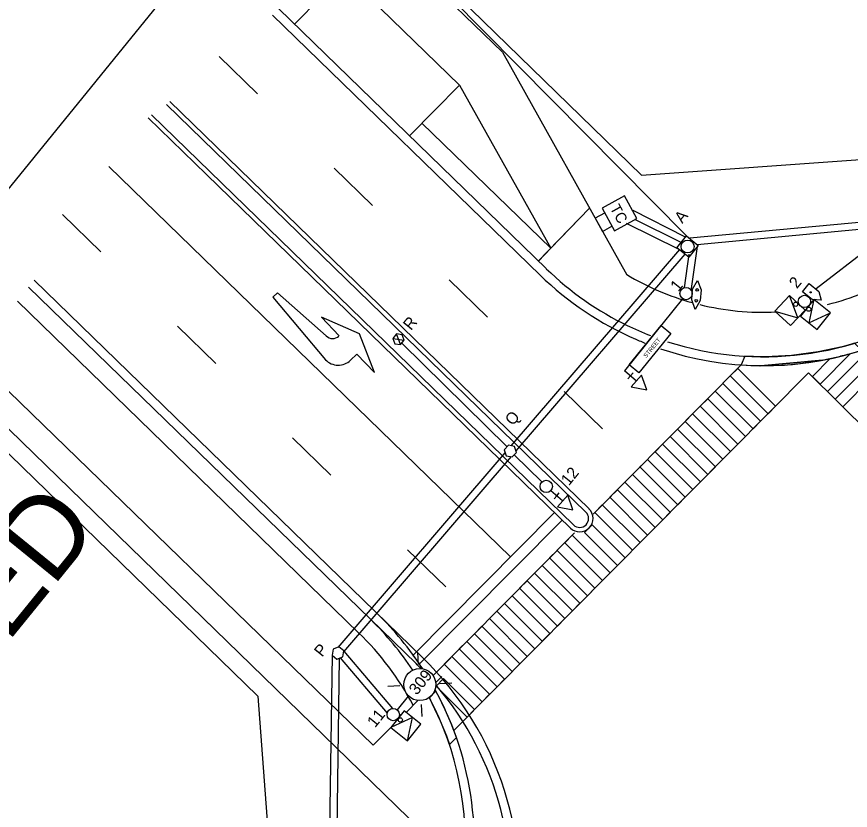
# Model space of a CAD drawing. Extents: x 592613 to 600223, y 4837996 to 4840103.
# Drawn here: x 592974.48 to 593021.3, y 4839324.28 to 4839368.84 of the extents above; entities that cross this region are included whole.
import ezdxf

# ---------------------------------------------------------------- set-up
doc = ezdxf.new("R2010")
doc.units = 0
for name, color, linetype in [('ENG_BORDER', 7, 'Continuous'), ('ENG_BUS-PAD', 7, 'Continuous'), ('ENG_CURB-BACK', 7, 'Continuous'), ('ENG_CURBSTOP', 7, 'Continuous'), ('ENG_EPAVT', 7, 'Continuous'), ('ENG_KILLSTRIP', 7, 'Continuous'), ('ENG_LIMITS', 7, 'Continuous'), ('ENG_MULTI-TRAIL', 7, 'Continuous'), ('ENG_SIDEWALK', 7, 'Continuous'), ('ENG_TX_TITLEBLOCK', 7, 'Continuous'), ('Level 12', 7, 'Continuous'), ('Level 9', 7, 'Continuous'), ('PMK_LANE', 7, 'Continuous'), ('PMK_LANE_3-6', 7, 'Continuous'), ('ROW_ENG_ROW', 7, 'Continuous'), ('TCS_100mm-NEW', 7, 'Continuous'), ('TCS_50mm-NEW', 7, 'Continuous'), ('TCS_75mm-NEW', 7, 'Continuous'), ('TCS_CONTROLLER', 7, 'Continuous'), ('TCS_ELEC-CHAMBER-NEW', 7, 'Continuous'), ('TCS_LUMINAIRE-NEW', 7, 'Continuous'), ('TCS_POLE-NEW', 7, 'Continuous'), ('TCS_PUSHBUTTON', 7, 'Continuous'), ('TCS_RADAR', 7, 'Continuous'), ('TCS_SIGN', 7, 'Continuous'), ('TCS_SIGNALHEAD', 7, 'Continuous')]:
    doc.layers.add(name, color=color, linetype=linetype)

msp = doc.modelspace()

# ---------------------------------------------------------------- linework, layer by layer
at = {"layer": 'ENG_BORDER'}
msp.add_lwpolyline([(593027.682, 4839425.246), (592902.303, 4839270.934)], dxfattribs=at)
at = {"layer": 'ENG_BUS-PAD'}
for p, q in [((592990.086, 4839368.429), (592992.903, 4839371.27)), ((592999.359, 4839364.998), (592992.903, 4839371.27)), ((592996.542, 4839362.158), (592999.359, 4839364.998))]:
    msp.add_line(p, q, dxfattribs=at)
at = {"layer": 'ENG_CURB-BACK'}
for p, q in [((593004.224, 4839354.695), (592989.203, 4839369.287)), ((593006.453, 4839341.028), (592982.896, 4839363.913)), ((593005.756, 4839340.311), (592982.062, 4839363.329)), ((592996.914, 4839332.519), (592975.154, 4839353.658))]:
    msp.add_line(p, q, dxfattribs=at)
for centre, radius, start, end in [((593016.418, 4839367.247), 17.5, 225.8289, 244.2197), ((593016.418, 4839367.247), 17.5, 252.0777, 302.4982), ((593016.418, 4839367.247), 17.5, 243.9292, 248.7697), ((593006.104, 4839340.669), 0.5, 315.8289, 45.8289), ((593006.104, 4839340.669), 0.5, 225.8289, 315.8289), ((592982.191, 4839322.423), 17.5, 33.7836, 45.8289), ((592982.191, 4839322.423), 16.5, 28.0452, 45.829), ((592984.72, 4839319.967), 17.5, 44.5335, 45.8289), ((592984.72, 4839319.967), 17.5, 348.3699, 40.5041), ((592982.191, 4839322.423), 17.5, 322.6377, 27.9119)]:
    msp.add_arc(centre, radius, start, end, dxfattribs=at)
at = {"layer": 'ENG_CURBSTOP'}
msp.add_lwpolyline([(592998.788, 4839327.972), (592999.181, 4839328.368), (592998.916, 4839329.079), (592998.689, 4839329.622), (592998.467, 4839330.11), (592998.144, 4839330.76), (592998.031, 4839330.976), (592998.031, 4839330.976), (592997.667, 4839330.609), (592997.798, 4839330.293), (592998.276, 4839329.318), (592998.617, 4839328.46)], close=True, dxfattribs=at)
at = {"layer": 'ENG_EPAVT'}
for p, q in [((593003.875, 4839354.337), (592988.856, 4839368.927)), ((593006.627, 4839341.207), (592983.09, 4839364.072)), ((593005.582, 4839340.131), (592985.14, 4839359.99)), ((592997.262, 4839332.877), (592975.469, 4839354.048)), ((592994.505, 4839327.934), (592972.006, 4839349.762)), ((592996.353, 4839329.785), (592997.016, 4839330.449)), ((592994.505, 4839327.934), (592995.501, 4839328.931))]:
    msp.add_line(p, q, dxfattribs=at)
for centre, radius, start, end in [((593016.418, 4839367.247), 18, 251.2988, 322.6377), ((593016.418, 4839367.247), 18, 225.8289, 246.5867), ((593016.418, 4839367.247), 18, 246.1583, 248.3127), ((593006.104, 4839340.669), 0.75, 315.8289, 45.8289), ((593006.104, 4839340.669), 0.75, 225.8289, 315.8289), ((592982.191, 4839322.423), 18, 33.0068, 45.8289), ((592984.72, 4839319.967), 18, 349.35, 45.8289), ((592982.191, 4839322.423), 18, 345.9453, 28.6887)]:
    msp.add_arc(centre, radius, start, end, dxfattribs=at)
at = {"layer": 'ENG_KILLSTRIP'}
for p, q in [((593004.478, 4839355.843), (592997.246, 4839362.868)), ((592993.689, 4839334.258), (592974.523, 4839352.877))]:
    msp.add_line(p, q, dxfattribs=at)
at = {"layer": 'ENG_LIMITS'}
msp.add_lwpolyline([(593021.943, 4839350.116), (593021.547, 4839350.517), (593021.305, 4839350.439), (593020.844, 4839350.315), (593019.495, 4839350.021), (593017.993, 4839349.811), (593016.907, 4839349.761), (593016.364, 4839349.736), (593015.377, 4839349.781), (593015.176, 4839349.29), (593015.718, 4839349.259), (593016.239, 4839349.25), (593016.733, 4839349.253), (593016.997, 4839349.255), (593017.455, 4839349.278), (593018.049, 4839349.323), (593018.648, 4839349.386), (593019.737, 4839349.555), (593016.278, 4839349.248), (593019.722, 4839349.553), (593019.968, 4839349.607), (593020.78, 4839349.784), (593021.472, 4839349.975)], close=True, dxfattribs=at)
at = {"layer": 'ENG_MULTI-TRAIL'}
for p, q in [((593001.763, 4839366.845), (592994.71, 4839373.697)), ((592999.359, 4839364.998), (593004.478, 4839355.843))]:
    msp.add_line(p, q, dxfattribs=at)
at = {"layer": 'ENG_SIDEWALK'}
for p, q in [((593001.763, 4839366.845), (593008.745, 4839354.358)), ((593006.659, 4839358.088), (593003.781, 4839355.125)), ((593004.478, 4839355.843), (593006.659, 4839358.088)), ((593003.789, 4839355.118), (593004.478, 4839355.843)), ((592997.171, 4839323.207), (592971.051, 4839348.581)), ((592998.019, 4839331.456), (592998.353, 4839331.793)), ((592996.393, 4839329.816), (592997.02, 4839330.449))]:
    msp.add_line(p, q, dxfattribs=at)
for start, end in [(239.233, 254.564), (283.8878, 300.1512), (256.2385, 272.6796)]:
    msp.add_arc((593016.418, 4839367.247), 15, start, end, dxfattribs=at)
at = {"layer": 'Level 12'}
for p, q in [((592989.135, 4839353.341), (592988.871, 4839353.087)), ((592988.871, 4839353.087), (592991.823, 4839349.582)), ((592991.872, 4839350.925), (592989.135, 4839353.341)), ((592993.744, 4839351.035), (592991.607, 4839351.965)), ((592991.607, 4839351.965), (592992.601, 4839350.93)), ((592994.588, 4839348.862), (592993.744, 4839351.035)), ((592993.237, 4839349.554), (592993.594, 4839349.897)), ((592993.594, 4839349.897), (592994.588, 4839348.862))]:
    msp.add_line(p, q, dxfattribs=at)
for centre, radius, start, end in [((592992.233, 4839351.271), 0.5, 223.8199, 313.8436), ((592992.543, 4839350.275), 1, 223.8262, 313.8484)]:
    msp.add_arc(centre, radius, start, end, dxfattribs=at)
at = {"layer": 'Level 9'}
msp.add_lwpolyline([(593012.724, 4839354.031), (593012.921, 4839353.502), (593012.873, 4839352.899), (593012.595, 4839352.407), (593012.398, 4839352.936), (593012.446, 4839353.54)], close=True, dxfattribs=at)
for centre in [(593012.701, 4839353.5), (593012.653, 4839352.896)]:
    msp.add_circle(centre, 0.075, dxfattribs=at)
at = {"layer": 'PMK_LANE'}
for p, q in [((592981.875, 4839363.172), (592985.14, 4839359.99)), ((593002.224, 4839338.514), (592979.661, 4839360.432)), ((593019.601, 4839348.214), (593021.3, 4839349.922)), ((593022.143, 4839349.918), (593020.026, 4839347.792)), ((593015.176, 4839349.29), (593006.856, 4839340.909)), ((593020.177, 4839349.644), (593019.175, 4839348.637)), ((593020.452, 4839347.369), (593022.568, 4839349.495)), ((593018.963, 4839348.848), (592999.034, 4839328.772)), ((593014.984, 4839349.097), (593014.561, 4839348.671)), ((593017.107, 4839346.978), (593014.984, 4839349.097)), ((593018.963, 4839348.848), (593040.707, 4839327.25)), ((593022.994, 4839349.072), (593020.878, 4839346.946)), ((593014.561, 4839348.671), (593016.685, 4839346.552)), ((593019.175, 4839348.637), (593019.601, 4839348.214)), ((593014.139, 4839348.246), (593013.716, 4839347.82)), ((593016.262, 4839346.126), (593014.139, 4839348.246)), ((593013.716, 4839347.82), (593015.839, 4839345.7)), ((593020.026, 4839347.792), (593020.452, 4839347.369)), ((593013.293, 4839347.394), (593012.871, 4839346.968)), ((593012.871, 4839346.968), (593014.994, 4839344.849)), ((593015.416, 4839345.275), (593013.293, 4839347.394)), ((593016.685, 4839346.552), (593017.107, 4839346.978)), ((593020.878, 4839346.946), (593021.303, 4839346.523)), ((593012.448, 4839346.542), (593012.025, 4839346.117)), ((593014.571, 4839344.423), (593012.448, 4839346.542)), ((593012.025, 4839346.117), (593014.148, 4839343.997)), ((593015.839, 4839345.7), (593016.262, 4839346.126)), ((593011.602, 4839345.691), (593011.18, 4839345.265)), ((593013.726, 4839343.571), (593011.602, 4839345.691)), ((593011.18, 4839345.265), (593013.303, 4839343.145)), ((593014.994, 4839344.849), (593015.416, 4839345.275)), ((593010.757, 4839344.839), (593010.334, 4839344.413)), ((593012.88, 4839342.72), (593010.757, 4839344.839)), ((593010.334, 4839344.413), (593012.457, 4839342.294)), ((593014.148, 4839343.997), (593014.571, 4839344.423)), ((593012.035, 4839341.868), (593009.912, 4839343.987)), ((593009.489, 4839343.562), (593011.612, 4839341.442)), ((593013.303, 4839343.145), (593013.726, 4839343.571)), ((593009.066, 4839343.136), (593008.643, 4839342.71)), ((593011.189, 4839341.016), (593009.066, 4839343.136)), ((593012.457, 4839342.294), (593012.88, 4839342.72)), ((593008.221, 4839342.284), (593007.798, 4839341.858)), ((593010.344, 4839340.165), (593008.221, 4839342.284)), ((593008.643, 4839342.71), (593010.767, 4839340.59)), ((593007.798, 4839341.858), (593009.921, 4839339.739)), ((593011.612, 4839341.442), (593012.035, 4839341.868)), ((593007.375, 4839341.432), (593006.953, 4839341.007)), ((593009.499, 4839339.313), (593007.375, 4839341.432)), ((593004.689, 4839340.998), (592996.753, 4839333.003)), ((593006.953, 4839341.007), (593009.076, 4839338.887)), ((593010.767, 4839340.59), (593011.189, 4839341.016)), ((593005.12, 4839340.58), (592997.103, 4839332.504)), ((593006.803, 4839340.31), (593006.38, 4839339.883)), ((593008.654, 4839338.462), (593006.803, 4839340.31)), ((593009.921, 4839339.739), (593010.344, 4839340.165)), ((593005.819, 4839339.865), (592997.867, 4839331.854)), ((593005.685, 4839339.729), (593005.262, 4839339.303)), ((593007.808, 4839337.61), (593005.685, 4839339.729)), ((593006.38, 4839339.883), (593008.23, 4839338.036)), ((593005.262, 4839339.303), (593007.385, 4839337.184)), ((593009.076, 4839338.887), (593009.499, 4839339.313)), ((593004.839, 4839338.878), (593004.416, 4839338.452)), ((593006.962, 4839336.758), (593004.839, 4839338.878)), ((593004.416, 4839338.452), (593006.54, 4839336.332)), ((593008.23, 4839338.036), (593008.654, 4839338.462)), ((593003.994, 4839338.026), (593003.571, 4839337.6)), ((593003.571, 4839337.6), (593005.694, 4839335.481)), ((593006.117, 4839335.906), (593003.994, 4839338.026)), ((593007.385, 4839337.184), (593007.808, 4839337.61)), ((593003.148, 4839337.174), (593002.726, 4839336.748)), ((593005.272, 4839335.055), (593003.148, 4839337.174)), ((593002.726, 4839336.748), (593004.849, 4839334.629)), ((593006.54, 4839336.332), (593006.962, 4839336.758)), ((593002.303, 4839336.323), (593001.88, 4839335.897)), ((593004.426, 4839334.203), (593002.303, 4839336.323)), ((593001.88, 4839335.897), (593004.003, 4839333.777)), ((593005.694, 4839335.481), (593006.117, 4839335.906)), ((593001.457, 4839335.471), (593001.035, 4839335.045)), ((593003.581, 4839333.352), (593001.457, 4839335.471)), ((593001.035, 4839335.045), (593003.158, 4839332.926)), ((593004.849, 4839334.629), (593005.272, 4839335.055)), ((593000.612, 4839334.619), (593000.189, 4839334.194)), ((593002.735, 4839332.5), (593000.612, 4839334.619)), ((593000.189, 4839334.194), (593002.313, 4839332.074)), ((593004.003, 4839333.777), (593004.426, 4839334.203)), ((592999.767, 4839333.768), (592999.344, 4839333.342)), ((593001.89, 4839331.648), (592999.767, 4839333.768)), ((592998.921, 4839332.916), (592998.499, 4839332.49)), ((593001.044, 4839330.797), (592998.921, 4839332.916)), ((592999.344, 4839333.342), (593001.467, 4839331.222)), ((593003.158, 4839332.926), (593003.581, 4839333.352)), ((592998.499, 4839332.49), (593000.622, 4839330.371)), ((593002.313, 4839332.074), (593002.735, 4839332.5)), ((592998.46, 4839331.683), (592998.036, 4839331.256)), ((593000.2, 4839329.946), (592998.46, 4839331.683)), ((593001.467, 4839331.222), (593001.89, 4839331.648)), ((592998.036, 4839331.256), (592999.776, 4839329.519)), ((593000.622, 4839330.371), (593001.044, 4839330.797)), ((592999.776, 4839329.519), (593000.2, 4839329.946))]:
    msp.add_line(p, q, dxfattribs=at)
for points in [[(593021.042, 4839349.851), (593021.044, 4839349.844), (593020.76, 4839349.779)], [(593009.912, 4839343.987), (593009.536, 4839343.609), (593009.489, 4839343.562)]]:
    msp.add_lwpolyline(points, dxfattribs=at)
msp.add_lwpolyline([(592996.753, 4839333.003), (593004.689, 4839340.998), (593005.12, 4839340.58), (592997.103, 4839332.504)], close=True, dxfattribs=at)
for start, end in [(282.0553, 283.9602), (284.8874, 285.7389)]:
    msp.add_arc((593016.418, 4839367.247), 18, start, end, dxfattribs=at)
at = {"layer": 'PMK_LANE_3-6'}
for p, q in [((592988.017, 4839364.514), (592985.865, 4839366.605)), ((592994.473, 4839358.243), (592992.321, 4839360.333)), ((592979.21, 4839355.643), (592977.058, 4839357.733)), ((593000.928, 4839351.971), (592998.776, 4839354.062)), ((592985.666, 4839349.371), (592983.514, 4839351.462)), ((593007.384, 4839345.7), (593005.232, 4839347.79)), ((592992.122, 4839343.099), (592989.97, 4839345.19)), ((592998.577, 4839336.828), (592996.425, 4839338.918))]:
    msp.add_line(p, q, dxfattribs=at)
at = {"layer": 'ROW_ENG_ROW'}
for p, q in [((593009.576, 4839359.952), (592994.095, 4839374.992)), ((593009.576, 4839359.952), (593029.37, 4839361.343)), ((592988.026, 4839330.697), (592970.362, 4839347.856)), ((592988.026, 4839330.697), (592989.681, 4839308.33))]:
    msp.add_line(p, q, dxfattribs=at)
at = {"layer": 'TCS_100mm-NEW'}
for p, q in [((593011.803, 4839356.17), (593009.198, 4839357.455)), ((593023.873, 4839357.487), (593012.289, 4839356.403)), ((593011.693, 4839355.766), (593008.73, 4839357.228)), ((593011.701, 4839355.762), (593002.244, 4839344.752)), ((593011.991, 4839353.627), (593012.25, 4839355.504)), ((593001.902, 4839344.354), (592992.52, 4839333.431)), ((593002.419, 4839344.239), (593003.987, 4839342.718)), ((592992.203, 4839332.991), (592991.935, 4839314.564)), ((592992.859, 4839333.212), (592995.595, 4839330.002))]:
    msp.add_line(p, q, dxfattribs=at)
at = {"layer": 'TCS_50mm-NEW'}
for p, q in [((593012.1, 4839356.536), (592994.052, 4839374.777)), ((593012.048, 4839356.472), (593009.1, 4839357.955)), ((593023.817, 4839357.08), (593012.71, 4839356.041)), ((593012.37, 4839353.447), (593012.715, 4839355.948)), ((593012.012, 4839355.511), (593002.519, 4839344.459)), ((593002.027, 4839344.698), (592996.111, 4839350.52)), ((593002.249, 4839344.144), (592992.842, 4839333.192)), ((592992.59, 4839332.818), (592992.338, 4839314.788)), ((592992.65, 4839332.841), (592995.296, 4839329.736))]:
    msp.add_line(p, q, dxfattribs=at)
at = {"layer": 'TCS_75mm-NEW'}
msp.add_line((593023.818, 4839356.99), (593019.379, 4839353.554), dxfattribs=at)
at = {"layer": 'TCS_CONTROLLER'}
for p, q in [((593008.623, 4839358.782), (593007.361, 4839358.089)), ((593009.316, 4839357.52), (593008.623, 4839358.782)), ((593007.505, 4839357.814), (593006.979, 4839357.525)), ((593007.361, 4839358.089), (593008.054, 4839356.827)), ((593006.979, 4839357.525), (593007.383, 4839356.789)), ((593008.054, 4839356.827), (593009.316, 4839357.52)), ((593007.383, 4839356.789), (593007.909, 4839357.077))]:
    msp.add_line(p, q, dxfattribs=at)
at = {"layer": 'TCS_ELEC-CHAMBER-NEW'}
for p, q in [((593011.564, 4839355.873), (593012.1, 4839356.536)), ((593012.1, 4839356.536), (593012.763, 4839356)), ((593012.227, 4839355.337), (593011.564, 4839355.873)), ((593012.763, 4839356), (593012.227, 4839355.337)), ((592995.812, 4839351.029), (592995.612, 4839350.781)), ((592995.612, 4839350.781), (592996.242, 4839350.682)), ((592995.612, 4839350.781), (592995.726, 4839350.483)), ((592996.041, 4839350.434), (592995.812, 4839351.029)), ((592996.127, 4839350.979), (592995.812, 4839351.029)), ((592996.041, 4839350.434), (592996.242, 4839350.682)), ((592996.242, 4839350.682), (592996.127, 4839350.979)), ((592995.726, 4839350.483), (592996.041, 4839350.434)), ((593002.098, 4839344.778), (593001.869, 4839344.52)), ((593002.437, 4839344.709), (593002.098, 4839344.778)), ((593002.546, 4839344.381), (593002.437, 4839344.709)), ((593001.869, 4839344.52), (593001.978, 4839344.192)), ((593001.978, 4839344.192), (593002.316, 4839344.122)), ((593002.316, 4839344.122), (593002.546, 4839344.381)), ((592992.581, 4839333.455), (592992.258, 4839333.332)), ((592992.849, 4839333.237), (592992.581, 4839333.455)), ((592992.258, 4839333.332), (592992.203, 4839332.991)), ((592992.203, 4839332.991), (592992.471, 4839332.773)), ((592992.471, 4839332.773), (592992.794, 4839332.896)), ((592992.794, 4839332.896), (592992.849, 4839333.237))]:
    msp.add_line(p, q, dxfattribs=at)
msp.add_circle((593012.163, 4839355.937), 0.361, dxfattribs=at)
at = {"layer": 'TCS_LUMINAIRE-NEW'}
for p, q in [((593011.887, 4839353.005), (593008.622, 4839348.964)), ((592997.058, 4839332.465), (592997.018, 4839333.139)), ((592996.004, 4839331.275), (592995.329, 4839331.234)), ((592998.248, 4839331.41), (592998.923, 4839331.451)), ((592995.866, 4839329.918), (592996.495, 4839330.694)), ((592997.194, 4839330.22), (592997.234, 4839329.546))]:
    msp.add_line(p, q, dxfattribs=at)
msp.add_circle((592997.126, 4839331.342), 0.9, dxfattribs=at)
at = {"layer": 'TCS_POLE-NEW'}
for centre in [(593012.077, 4839353.297), (593018.728, 4839352.858), (593004.229, 4839342.472), (592995.633, 4839329.658)]:
    msp.add_circle(centre, 0.346, dxfattribs=at)
at = {"layer": 'TCS_PUSHBUTTON'}
for centre in [(593018.235, 4839352.699), (593018.971, 4839352.42), (592996.03, 4839329.359)]:
    msp.add_circle(centre, 0.12, dxfattribs=at)
at = {"layer": 'TCS_RADAR'}
msp.add_lwpolyline([(593018.616, 4839353.402), (593018.991, 4839353.863), (593019.533, 4839353.422), (593019.663, 4839352.923), (593019.158, 4839352.962)], close=True, dxfattribs=at)
msp.add_circle((593019.076, 4839353.367), 0.0323, dxfattribs=at)
at = {"layer": 'TCS_SIGN'}
msp.add_lwpolyline([(593008.886, 4839349.294), (593010.675, 4839351.506), (593011.222, 4839351.064), (593009.434, 4839348.851)], close=True, dxfattribs=at)
at = {"layer": 'TCS_SIGNALHEAD'}
for p, q in [((593018.758, 4839352.374), (593017.881, 4839353.194)), ((593019.255, 4839352.962), (593018.501, 4839352.029)), ((593017.062, 4839352.317), (593017.938, 4839351.498)), ((593017.938, 4839351.498), (593018.758, 4839352.374)), ((593019.434, 4839351.275), (593020.188, 4839352.208)), ((593018.501, 4839352.029), (593019.434, 4839351.275)), ((593009.29, 4839348.385), (593008.623, 4839348.963)), ((593008.956, 4839348.674), (593009.101, 4839348.841)), ((593008.956, 4839348.674), (593008.812, 4839348.507)), ((593009.579, 4839348.719), (593009.002, 4839348.052)), ((593009.868, 4839347.884), (593009.579, 4839348.719)), ((593009.002, 4839348.052), (593009.868, 4839347.884)), ((593005.145, 4839341.652), (593004.478, 4839342.231)), ((593004.811, 4839341.941), (593004.667, 4839341.775)), ((593004.811, 4839341.941), (593004.956, 4839342.108)), ((593005.434, 4839341.987), (593004.857, 4839341.319)), ((593005.723, 4839341.152), (593005.434, 4839341.987)), ((593004.857, 4839341.319), (593005.723, 4839341.152)), ((592996.251, 4839329.868), (592995.497, 4839328.935)), ((592997.184, 4839329.114), (592996.251, 4839329.868)), ((592996.43, 4839328.18), (592997.184, 4839329.114))]:
    msp.add_line(p, q, dxfattribs=at)
for points in [[(593017.881, 4839353.194), (593017.062, 4839352.317), (593018.348, 4839351.936), (593018.348, 4839351.936)], [(593020.188, 4839352.208), (593019.255, 4839352.962), (593018.967, 4839351.652), (593018.967, 4839351.652)], [(593009.579, 4839348.719), (593009.002, 4839348.052), (593009.868, 4839347.884), (593009.868, 4839347.884)], [(593005.434, 4839341.987), (593004.857, 4839341.319), (593005.723, 4839341.152), (593005.723, 4839341.152)], [(592995.497, 4839328.935), (592996.43, 4839328.18), (592996.717, 4839329.491), (592996.717, 4839329.491)]]:
    msp.add_lwpolyline(points, close=True, dxfattribs=at)

# ---------------------------------------------------------------- texts
at = {"layer": 'ENG_TX_TITLEBLOCK'}
msp.add_text('AS CONSTRUCTED', height=4.52865, rotation=50.906, dxfattribs=at).set_placement((592943.824, 4839296.556))
at = {"layer": 'TCS_CONTROLLER'}
msp.add_text('TC', height=0.6, rotation=298.7685, dxfattribs=at).set_placement((593007.784, 4839358.102))
at = {"layer": 'TCS_ELEC-CHAMBER-NEW'}
for s, p in [('A', (593011.867, 4839357.198)), ('R', (592996.631, 4839351.19)), ('Q', (593002.355, 4839345.842)), ('P', (592991.637, 4839332.851))]:
    msp.add_text(s, height=0.65, rotation=51.0574, dxfattribs=at).set_placement(p)
at = {"layer": 'TCS_LUMINAIRE-NEW'}
msp.add_text('309', height=0.65, rotation=51.283, dxfattribs=at).set_placement((592996.957, 4839330.714))
at = {"layer": 'TCS_POLE-NEW'}
for s, p in [('1', (593011.643, 4839353.366)), ('2', (593018.307, 4839353.537)), ('12', (593005.498, 4839342.473)), ('11', (592994.611, 4839328.886))]:
    msp.add_text(s, height=0.65, rotation=51.0574, dxfattribs=at).set_placement(p)
at = {"layer": 'TCS_SIGN'}
msp.add_text('STREET', height=0.2407, rotation=51.0574, dxfattribs=at).set_placement((593009.845, 4839349.663))

doc.saveas('drawing.dxf')
